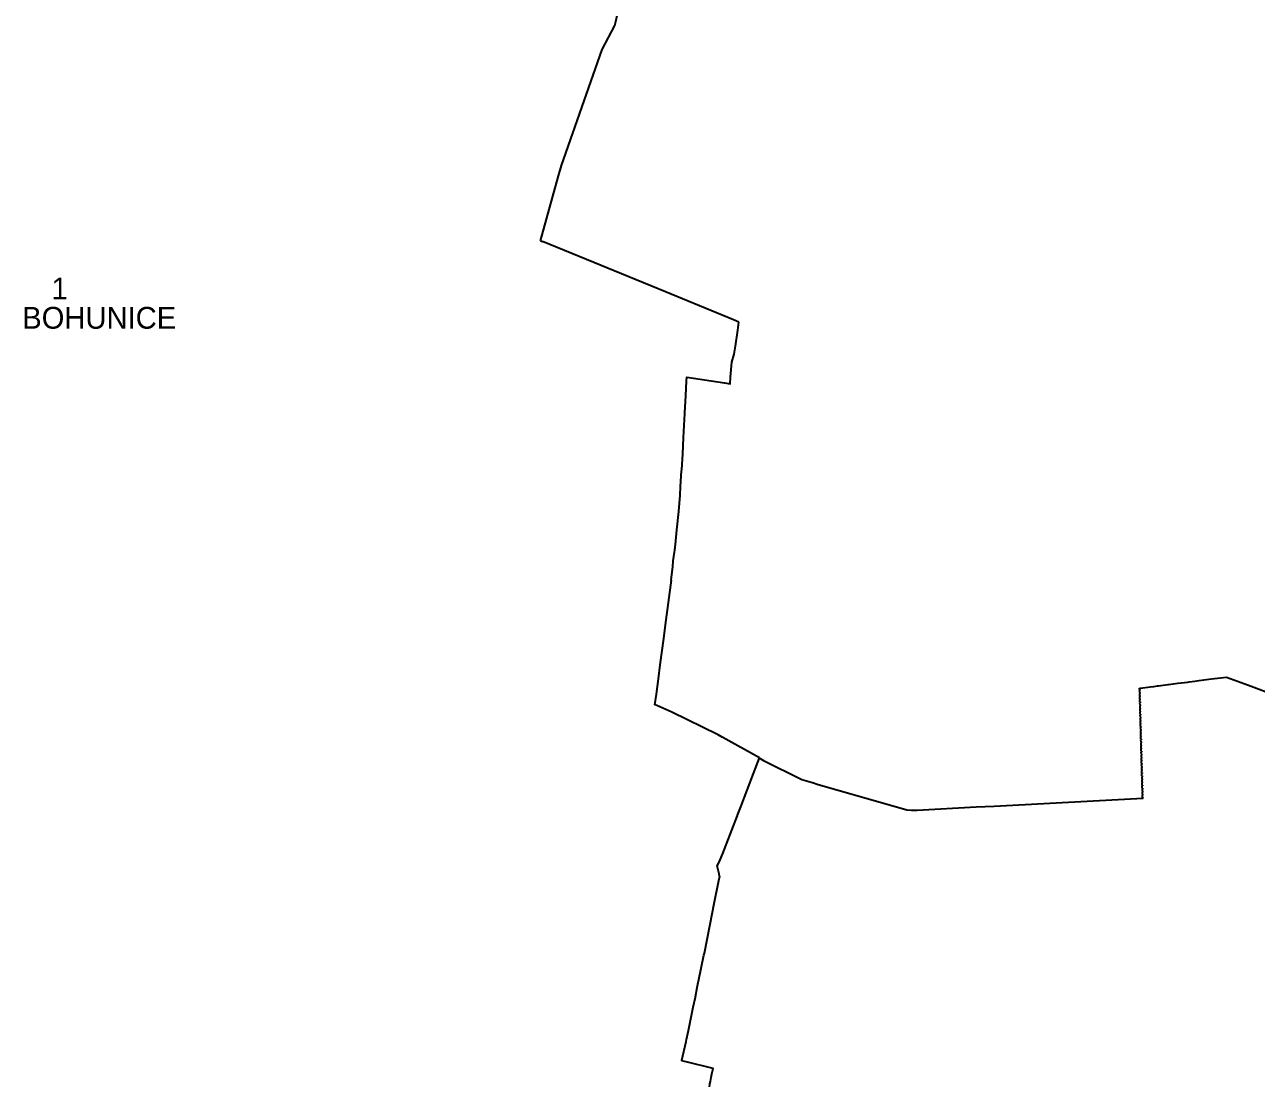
# Model space of a CAD drawing. Extents: x -610940 to -588976, y -1170376 to -1149800.
# Drawn here: x -600485 to -599073, y -1164281 to -1163066 of the extents above; entities that cross this region are included whole.
import ezdxf

# ---------------------------------------------------------------- set-up
doc = ezdxf.new("R2010")
doc.units = 0
doc.header["$LTSCALE"] = 10
doc.layers.add('54', color=7, linetype='Continuous', lineweight=35)
doc.layers.add('55', color=7, linetype='Continuous')
doc.layers.add('56', color=7, linetype='Continuous')

msp = doc.modelspace()

# ---------------------------------------------------------------- linework, layer by layer
at = {"layer": '54'}
for p, q in [((-599822.64, -1163094.58), (-599808.28, -1163067.14)), ((-599893.34, -1163313.66), (-599891.29, -1163314.5)), ((-599750.34, -1163372.19), (-599891.29, -1163314.5)), ((-599190.38, -1163824.19), (-599186.3, -1163823.66)), ((-599186.3, -1163823.66), (-599185.5, -1163823.56)), ((-599185.5, -1163823.56), (-599185.12, -1163823.51)), ((-599185.12, -1163823.51), (-599174.32, -1163822.11)), ((-599174.32, -1163822.11), (-599173.56, -1163822.01)), ((-599173.56, -1163822.01), (-599162.98, -1163820.65)), ((-599162.98, -1163820.65), (-599151.49, -1163819.16)), ((-599151.49, -1163819.16), (-599150.07, -1163818.98)), ((-599150.07, -1163818.98), (-599143.32, -1163818.14)), ((-599143.32, -1163818.14), (-599139.02, -1163817.61)), ((-599139.02, -1163817.61), (-599124.38, -1163815.69)), ((-599124.38, -1163815.69), (-599107.25, -1163813.44)), ((-599107.25, -1163813.44), (-599082.01, -1163822.83)), ((-599082.01, -1163822.83), (-599049.43, -1163834.91)), ((-599206.84, -1163826.29), (-599203.21, -1163825.84)), ((-599206.8, -1163827.81), (-599206.84, -1163826.29)), ((-599206.3, -1163827.8), (-599206.8, -1163827.81)), ((-599206.77, -1163828.81), (-599206.27, -1163828.8)), ((-599206.7, -1163831.34), (-599206.77, -1163828.81)), ((-599206.2, -1163831.33), (-599206.7, -1163831.34)), ((-599206.68, -1163832.34), (-599206.18, -1163832.33)), ((-599206.61, -1163834.87), (-599206.68, -1163832.34)), ((-599206.11, -1163834.86), (-599206.61, -1163834.87)), ((-599206.58, -1163835.87), (-599206.08, -1163835.86)), ((-599206.51, -1163838.4), (-599206.58, -1163835.87)), ((-599206.27, -1163828.8), (-599206.3, -1163827.8)), ((-599206.18, -1163832.33), (-599206.2, -1163831.33)), ((-599206.08, -1163835.86), (-599206.11, -1163834.86)), ((-599203.21, -1163825.84), (-599197.39, -1163825.09)), ((-599197.39, -1163825.09), (-599194.73, -1163824.75)), ((-599194.73, -1163824.75), (-599190.38, -1163824.19)), ((-599206.01, -1163838.39), (-599206.51, -1163838.4)), ((-599206.48, -1163839.4), (-599205.98, -1163839.39)), ((-599206.41, -1163841.93), (-599206.48, -1163839.4)), ((-599205.91, -1163841.91), (-599206.41, -1163841.93)), ((-599206.38, -1163842.93), (-599205.88, -1163842.91)), ((-599206.31, -1163845.46), (-599206.38, -1163842.93)), ((-599205.81, -1163845.44), (-599206.31, -1163845.46)), ((-599206.29, -1163846.46), (-599205.79, -1163846.44)), ((-599206.22, -1163848.99), (-599206.29, -1163846.46)), ((-599205.72, -1163848.97), (-599206.22, -1163848.99)), ((-599206.19, -1163849.99), (-599205.69, -1163849.97)), ((-599206.12, -1163852.51), (-599206.19, -1163849.99)), ((-599205.98, -1163839.39), (-599206.01, -1163838.39)), ((-599205.88, -1163842.91), (-599205.91, -1163841.91)), ((-599205.79, -1163846.44), (-599205.81, -1163845.44)), ((-599205.69, -1163849.97), (-599205.72, -1163848.97)), ((-599205.62, -1163852.5), (-599206.12, -1163852.51)), ((-599206.09, -1163853.51), (-599205.59, -1163853.5)), ((-599206.02, -1163856.04), (-599206.09, -1163853.51)), ((-599205.52, -1163856.03), (-599206.02, -1163856.04)), ((-599205.99, -1163857.04), (-599205.49, -1163857.03)), ((-599205.92, -1163859.57), (-599205.99, -1163857.04)), ((-599205.42, -1163859.56), (-599205.92, -1163859.57)), ((-599205.89, -1163860.57), (-599205.39, -1163860.56)), ((-599205.82, -1163863.1), (-599205.89, -1163860.57)), ((-599205.32, -1163863.09), (-599205.82, -1163863.1)), ((-599205.8, -1163864.1), (-599205.3, -1163864.09)), ((-599205.73, -1163866.63), (-599205.8, -1163864.1)), ((-599205.59, -1163853.5), (-599205.62, -1163852.5)), ((-599205.49, -1163857.03), (-599205.52, -1163856.03)), ((-599205.39, -1163860.56), (-599205.42, -1163859.56)), ((-599205.3, -1163864.09), (-599205.32, -1163863.09)), ((-599205.23, -1163866.61), (-599205.73, -1163866.63)), ((-599205.7, -1163867.63), (-599205.2, -1163867.61)), ((-599205.63, -1163870.16), (-599205.7, -1163867.63)), ((-599205.13, -1163870.14), (-599205.63, -1163870.16)), ((-599205.6, -1163871.16), (-599205.1, -1163871.14)), ((-599205.53, -1163873.69), (-599205.6, -1163871.16)), ((-599205.03, -1163873.67), (-599205.53, -1163873.69)), ((-599205.5, -1163874.69), (-599205, -1163874.67)), ((-599205.43, -1163877.22), (-599205.5, -1163874.69)), ((-599204.93, -1163877.2), (-599205.43, -1163877.22)), ((-599205.4, -1163878.21), (-599204.9, -1163878.2)), ((-599205.34, -1163880.74), (-599205.4, -1163878.21)), ((-599205.2, -1163867.61), (-599205.23, -1163866.61)), ((-599205.1, -1163871.14), (-599205.13, -1163870.14)), ((-599205, -1163874.67), (-599205.03, -1163873.67)), ((-599204.9, -1163878.2), (-599204.93, -1163877.2)), ((-599204.84, -1163880.73), (-599205.34, -1163880.74)), ((-599205.31, -1163881.74), (-599204.81, -1163881.73)), ((-599205.24, -1163884.27), (-599205.31, -1163881.74)), ((-599204.74, -1163884.26), (-599205.24, -1163884.27)), ((-599205.21, -1163885.27), (-599204.71, -1163885.26)), ((-599205.14, -1163887.8), (-599205.21, -1163885.27)), ((-599204.64, -1163887.79), (-599205.14, -1163887.8)), ((-599205.11, -1163888.8), (-599204.61, -1163888.79)), ((-599205.04, -1163891.33), (-599205.11, -1163888.8)), ((-599204.54, -1163891.32), (-599205.04, -1163891.33)), ((-599205.01, -1163892.33), (-599204.51, -1163892.32)), ((-599204.94, -1163894.86), (-599205.01, -1163892.33)), ((-599204.81, -1163881.73), (-599204.84, -1163880.73)), ((-599204.71, -1163885.26), (-599204.74, -1163884.26)), ((-599204.61, -1163888.79), (-599204.64, -1163887.79)), ((-599204.51, -1163892.32), (-599204.54, -1163891.32)), ((-599642.61, -1163906.19), (-599641.74, -1163906.73)), ((-599641.74, -1163906.73), (-599638, -1163909.08)), ((-599204.44, -1163894.84), (-599204.94, -1163894.86)), ((-599204.92, -1163895.86), (-599204.42, -1163895.84)), ((-599204.85, -1163898.39), (-599204.92, -1163895.86)), ((-599204.35, -1163898.37), (-599204.85, -1163898.39)), ((-599204.82, -1163899.39), (-599204.32, -1163899.37)), ((-599204.75, -1163901.92), (-599204.82, -1163899.39)), ((-599204.25, -1163901.9), (-599204.75, -1163901.92)), ((-599204.72, -1163902.92), (-599204.22, -1163902.9)), ((-599204.65, -1163905.35), (-599204.72, -1163902.92)), ((-599204.15, -1163905.43), (-599204.65, -1163905.35)), ((-599204.62, -1163906.44), (-599204.12, -1163906.43)), ((-599204.55, -1163908.97), (-599204.62, -1163906.44)), ((-599204.42, -1163895.84), (-599204.44, -1163894.84)), ((-599204.32, -1163899.37), (-599204.35, -1163898.37)), ((-599204.22, -1163902.9), (-599204.25, -1163901.9)), ((-599204.12, -1163906.43), (-599204.15, -1163905.43)), ((-599638, -1163909.08), (-599593.78, -1163930.98)), ((-599204.05, -1163908.96), (-599204.55, -1163908.97)), ((-599204.52, -1163909.97), (-599204.02, -1163909.96)), ((-599204.45, -1163912.5), (-599204.52, -1163909.97)), ((-599203.95, -1163912.49), (-599204.45, -1163912.5)), ((-599204.43, -1163913.5), (-599203.93, -1163913.49)), ((-599204.36, -1163916.03), (-599204.43, -1163913.5)), ((-599203.86, -1163916.02), (-599204.36, -1163916.03)), ((-599204.33, -1163917.03), (-599203.83, -1163917.02)), ((-599204.26, -1163919.56), (-599204.33, -1163917.03)), ((-599203.76, -1163919.55), (-599204.26, -1163919.56)), ((-599204.23, -1163920.56), (-599203.73, -1163920.54)), ((-599204.16, -1163923.09), (-599204.23, -1163920.56)), ((-599204.02, -1163909.96), (-599204.05, -1163908.96)), ((-599203.93, -1163913.49), (-599203.95, -1163912.49)), ((-599203.83, -1163917.02), (-599203.86, -1163916.02)), ((-599203.73, -1163920.54), (-599203.76, -1163919.55)), ((-599593.78, -1163930.98), (-599580.4, -1163934.82)), ((-599580.4, -1163934.82), (-599576.21, -1163936.03)), ((-599576.21, -1163936.03), (-599473.49, -1163965.55)), ((-599203.66, -1163923.07), (-599204.16, -1163923.09)), ((-599204.13, -1163924.09), (-599203.63, -1163924.07)), ((-599204.06, -1163926.62), (-599204.13, -1163924.09)), ((-599203.56, -1163926.6), (-599204.06, -1163926.62)), ((-599204.03, -1163927.61), (-599203.53, -1163927.6)), ((-599203.97, -1163930.14), (-599204.03, -1163927.61)), ((-599203.47, -1163930.13), (-599203.97, -1163930.14)), ((-599203.94, -1163931.14), (-599203.44, -1163931.13)), ((-599203.87, -1163933.67), (-599203.94, -1163931.14)), ((-599203.37, -1163933.66), (-599203.87, -1163933.67)), ((-599203.84, -1163934.67), (-599203.34, -1163934.66)), ((-599203.77, -1163937.2), (-599203.84, -1163934.67)), ((-599203.63, -1163924.07), (-599203.66, -1163923.07)), ((-599203.53, -1163927.6), (-599203.56, -1163926.6)), ((-599203.44, -1163931.13), (-599203.47, -1163930.13)), ((-599203.34, -1163934.66), (-599203.37, -1163933.66)), ((-599203.27, -1163937.19), (-599203.77, -1163937.2)), ((-599203.74, -1163938.2), (-599203.24, -1163938.19)), ((-599203.67, -1163940.73), (-599203.74, -1163938.2)), ((-599203.17, -1163940.72), (-599203.67, -1163940.73)), ((-599203.64, -1163941.73), (-599203.14, -1163941.72)), ((-599203.57, -1163944.26), (-599203.64, -1163941.73)), ((-599203.07, -1163944.25), (-599203.57, -1163944.26)), ((-599203.55, -1163945.26), (-599203.05, -1163945.25)), ((-599203.48, -1163947.79), (-599203.55, -1163945.26)), ((-599202.98, -1163947.77), (-599203.48, -1163947.79)), ((-599203.45, -1163948.79), (-599202.95, -1163948.77)), ((-599203.38, -1163951.32), (-599203.45, -1163948.79)), ((-599203.24, -1163938.19), (-599203.27, -1163937.19)), ((-599203.14, -1163941.72), (-599203.17, -1163940.72)), ((-599203.05, -1163945.25), (-599203.07, -1163944.25)), ((-599202.95, -1163948.77), (-599202.98, -1163947.77)), ((-599667.63, -1163971.54), (-599663.84, -1163962.02)), ((-599461.6, -1163965.79), (-599394.1, -1163962.25)), ((-599394.1, -1163962.25), (-599373.39, -1163961.22)), ((-599373.39, -1163961.22), (-599252.73, -1163954.94)), ((-599252.73, -1163954.94), (-599209.85, -1163952.67)), ((-599209.85, -1163952.67), (-599203.91, -1163952.36)), ((-599203.91, -1163952.36), (-599202.85, -1163952.3)), ((-599202.88, -1163951.3), (-599203.38, -1163951.32)), ((-599202.85, -1163952.3), (-599202.88, -1163951.3)), ((-599473.49, -1163965.55), (-599468.39, -1163966.11)), ((-599468.39, -1163966.11), (-599461.6, -1163965.79)), ((-599688.82, -1164038.73), (-599690.93, -1164029.78)), ((-599694.72, -1164074.59), (-599688.57, -1164044.62)), ((-599688.57, -1164044.62), (-599688.32, -1164043.11)), ((-599688.14, -1164042.07), (-599688.32, -1164043.11)), ((-599723.98, -1164218.41), (-599720.55, -1164201.11)), ((-599731.42, -1164252.95), (-599731.3, -1164252.48)), ((-599698.76, -1164276.65), (-599697.91, -1164272.02)), ((-599697.91, -1164272.02), (-599697.06, -1164267.83)), ((-599699.25, -1164279.34), (-599698.76, -1164276.65))]:
    msp.add_line(p, q, dxfattribs=at)
for points in [[(-599808.28, -1163067.14), (-599807.2, -1163062.59), (-599804.73, -1163052.14)], [(-599869.5, -1163227.69), (-599840.71, -1163145.85), (-599822.64, -1163094.58)], [(-599893.34, -1163313.66), (-599872.69, -1163239.37), (-599869.5, -1163227.69)], [(-599666.17, -1163406.83), (-599672.27, -1163404.25), (-599750.34, -1163372.19)], [(-599728.09, -1163511.02), (-599727.05, -1163491.28), (-599726.12, -1163474.01), (-599725.9, -1163469.96), (-599682.56, -1163476.52), (-599676.16, -1163477.47), (-599675.66, -1163469.87), (-599674.06, -1163452.93), (-599671.36, -1163443.5), (-599669.98, -1163434.52), (-599667.41, -1163416.24), (-599666.17, -1163406.83)], [(-599733.43, -1163605.13), (-599732.86, -1163595.31), (-599731.69, -1163577.42), (-599731.55, -1163575.78), (-599730.41, -1163558.13), (-599729.58, -1163539.1), (-599728.11, -1163511.52), (-599728.09, -1163511.02)], [(-599738.44, -1163657.35), (-599737.17, -1163645.02), (-599734.88, -1163623.85), (-599733.43, -1163605.13)], [(-599741.78, -1163687.17), (-599741.32, -1163680.26), (-599739.67, -1163670.31), (-599739.42, -1163668.17)], [(-599739.42, -1163668.17), (-599738.47, -1163657.68), (-599738.44, -1163657.35)], [(-599743.81, -1163702.61), (-599742.11, -1163689.78), (-599741.78, -1163687.17)], [(-599743.81, -1163702.61), (-599750.64, -1163753.58), (-599752.65, -1163769.45), (-599756.61, -1163799.54), (-599758.7, -1163815.44), (-599761.03, -1163833.19), (-599762.84, -1163845.15)], [(-599760.23, -1163846.16), (-599762.2, -1163845.34), (-599762.84, -1163845.15)], [(-599642.61, -1163906.19), (-599684.31, -1163882.84), (-599685.05, -1163882.38), (-599689.95, -1163879.57), (-599743.1, -1163853.79), (-599760.23, -1163846.16)], [(-599663.84, -1163962.02), (-599649.36, -1163923.95), (-599642.61, -1163906.19)], [(-599680.77, -1164005.81), (-599667.78, -1163971.91), (-599667.63, -1163971.54)], [(-599687.52, -1164023.01), (-599684.64, -1164015.59), (-599680.77, -1164005.81)], [(-599690.93, -1164029.78), (-599687.63, -1164023.22), (-599687.52, -1164023.01)], [(-599688.14, -1164042.07), (-599688.28, -1164041.4), (-599688.82, -1164038.73)], [(-599705.65, -1164129.67), (-599696.43, -1164082.92), (-599694.72, -1164074.59)], [(-599713.71, -1164169.13), (-599712.61, -1164163.25), (-599712.3, -1164161.72), (-599706.15, -1164132.22), (-599705.65, -1164129.67)], [(-599715.93, -1164180.29), (-599715.88, -1164180.06), (-599715.79, -1164179.59), (-599713.71, -1164169.13)], [(-599720.55, -1164201.11), (-599718.42, -1164191.52), (-599715.93, -1164180.29)], [(-599731.3, -1164252.48), (-599726.64, -1164230.93), (-599726.13, -1164228.54), (-599723.98, -1164218.41)], [(-599698.61, -1164261.08), (-599723.56, -1164254.91), (-599731.42, -1164252.95)], [(-599697.06, -1164267.83), (-599695.66, -1164261.68), (-599698.61, -1164261.08)], [(-599699.88, -1164282.95), (-599699.39, -1164280.28), (-599699.25, -1164279.34)]]:
    msp.add_lwpolyline(points, dxfattribs=at)

# ---------------------------------------------------------------- texts
at = {"layer": '55'}
msp.add_text('BOHUNICE ', height=25, dxfattribs=at).set_placement((-600487.43, -1163414.5))
at = {"layer": '56'}
msp.add_text('1 ', height=25, dxfattribs=at).set_placement((-600453.84, -1163380.9))

doc.saveas('drawing.dxf')
